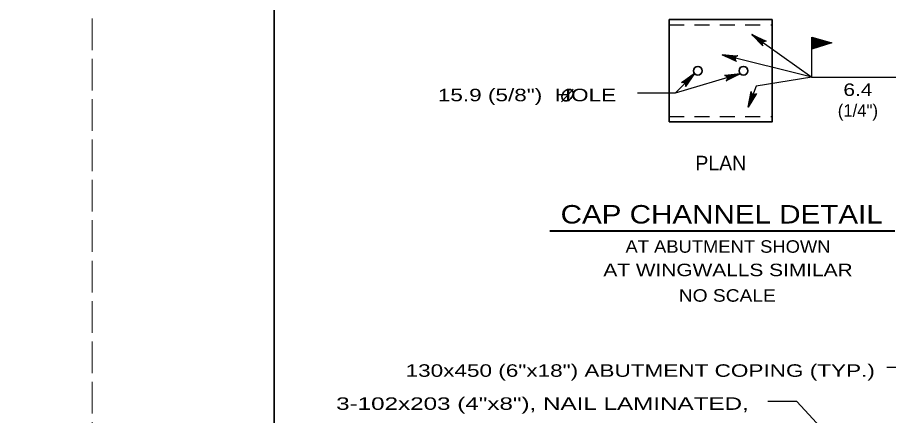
# Model space of a CAD drawing. Extents: x -6.4 to 73.1, y -66 to 0.
# Drawn here: x 33.28 to 41.66, y -58.66 to -54.84 of the extents above; entities that cross this region are included whole.
import ezdxf
from ezdxf.enums import TextEntityAlignment as Align

# ---------------------------------------------------------------- set-up
doc = ezdxf.new("R2010")
doc.units = 0
doc.header["$LTSCALE"] = 0.048
doc.linetypes.add('LONG_DASHED', pattern=[7.5, 6, -1.5])
doc.linetypes.add('MEDIUM_DASHED', pattern=[4.5, 3, -1.5])
for name, color, linetype, lineweight in [('1', 7, 'Continuous', 13), ('3', 7, 'Continuous', 35), ('4', 7, 'Continuous', 25), ('5', 7, 'Continuous', 25), ('63', 7, 'LONG_DASHED', 13)]:
    doc.layers.add(name, color=color, linetype=linetype, lineweight=lineweight)

msp = doc.modelspace()

# ---------------------------------------------------------------- linework, layer by layer
at = {"layer": '1', "lineweight": 35}
msp.add_lwpolyline([(35.75, -65.25), (67.25, -65.25), (67.25, -44.75), (35.75, -44.75)], close=True, dxfattribs=at)
at = {"layer": '3'}
for q in [(40.53625, -54.85908), (39.54658, -55.84308)]:
    msp.add_line((39.54658, -54.85908), q, dxfattribs=at)
at = {"layer": '3', "linetype": 'MEDIUM_DASHED', "lineweight": 25}
for p, q in [((39.54658, -54.91033), (40.53625, -54.91033)), ((39.54658, -55.79183), (40.53625, -55.79183))]:
    msp.add_line(p, q, dxfattribs=at)
at = {"layer": '3', "lineweight": 25}
for p, q in [((40.34167, -55.00233), (40.91958, -55.41417)), ((40.91958, -55.41417), (40.05517, -55.19875)), ((40.91958, -55.41417), (40.382, -55.50025)), ((40.91958, -55.41417), (42.10517, -55.41417)), ((40.382, -55.50025), (40.30683, -55.69967))]:
    msp.add_line(p, q, dxfattribs=at)
at = {"layer": '3'}
msp.add_lwpolyline([(39.54658, -55.84308), (40.53625, -55.84308), (40.53625, -54.85908)], dxfattribs=at)
at = {"layer": '3', "lineweight": 25}
msp.add_lwpolyline([(40.91958, -55.41417), (40.91958, -55.03017), (41.112, -55.08375), (40.91942, -55.1425), (40.92308, -55.0365), (41.09667, -55.08358), (40.92433, -55.135), (40.92433, -55.04142), (41.08617, -55.083), (40.92742, -55.13008), (40.92683, -55.047), (41.07308, -55.08358), (40.92992, -55.12508), (40.92933, -55.05383), (41.05633, -55.083), (40.94042, -55.11275), (40.933, -55.05875), (41.04525, -55.08175), (40.938, -55.11833), (40.93675, -55.06558), (41.03408, -55.08175), (40.94233, -55.11025), (40.93983, -55.07058), (41.02167, -55.08175), (40.94542, -55.1065), (40.94233, -55.073), (41.01108, -55.08175), (40.94667, -55.10283), (40.94667, -55.078), (41.00058, -55.08233), (40.94975, -55.09783), (40.94975, -55.08108), (40.98567, -55.08417), (40.95158, -55.09475), (40.95283, -55.08608), (40.97458, -55.08542), (40.95225, -55.09225), (40.95408, -55.08792), (41.10533, -55.08358), (40.9225, -55.13817), (40.92183, -55.03333)], dxfattribs=at)
at = {"layer": '3'}
for centre in [(39.82227, -55.3511), (40.26056, -55.3511)]:
    msp.add_circle(centre, 0.04217, dxfattribs=at)
at = {"layer": '4'}
for p, q in [((40.23025, -55.38042), (39.60375, -55.56533)), ((41.54783, -59.35875), (40.77258, -58.52733))]:
    msp.add_line(p, q, dxfattribs=at)
at = {"layer": '4', "lineweight": 40}
msp.add_line((38.4005, -56.88883), (41.71642, -56.88883), dxfattribs=at)
at = {"layer": '4'}
for points in [[(40.34167, -55.00233), (40.47933, -55.06617), (40.47233, -55.06608), (40.46533, -55.066), (40.46, -55.06833), (40.45467, -55.07067), (40.45108, -55.07425), (40.4475, -55.07783), (40.44533, -55.08242), (40.44308, -55.08692), (40.44258, -55.09275), (40.44208, -55.0985), (40.4445, -55.10508), (40.44683, -55.11167), (40.34167, -55.00233), (40.4445, -55.10508), (40.44208, -55.0985), (40.34167, -55.00233), (40.44258, -55.09275), (40.44308, -55.08692), (40.34167, -55.00233), (40.44533, -55.08242), (40.4475, -55.07783), (40.34167, -55.00233), (40.45108, -55.07425), (40.45467, -55.07067), (40.34167, -55.00233), (40.46, -55.06833), (40.46533, -55.066), (40.34167, -55.00233), (40.47233, -55.06608)], [(40.05517, -55.19883), (40.20667, -55.20675), (40.20017, -55.20925), (40.19367, -55.21175), (40.18958, -55.21592), (40.1855, -55.22008), (40.1835, -55.22475), (40.1815, -55.22942), (40.18117, -55.2345), (40.18083, -55.2395), (40.1825, -55.24508), (40.18425, -55.25067), (40.18883, -55.25583), (40.1935, -55.26108), (40.05517, -55.19883), (40.18883, -55.25583), (40.18425, -55.25067), (40.05517, -55.19883), (40.1825, -55.24508), (40.18083, -55.2395), (40.05517, -55.19883), (40.18117, -55.2345), (40.1815, -55.22942), (40.05517, -55.19883), (40.1835, -55.22475), (40.1855, -55.22008), (40.05517, -55.19883), (40.18958, -55.21592), (40.19367, -55.21175), (40.05517, -55.19883), (40.20017, -55.20925)], [(39.78975, -55.37792), (39.60375, -55.56533), (39.24375, -55.56533)], [(39.78975, -55.37792), (39.7045, -55.5035), (39.70575, -55.49658), (39.707, -55.48975), (39.7055, -55.48408), (39.70408, -55.4785), (39.70108, -55.47433), (39.69817, -55.47025), (39.694, -55.46733), (39.68983, -55.46442), (39.68425, -55.463), (39.67858, -55.46158), (39.67175, -55.46283), (39.66483, -55.46408), (39.78975, -55.37792), (39.67175, -55.46283), (39.67858, -55.46158), (39.78975, -55.37792), (39.68425, -55.463), (39.68983, -55.46442), (39.78975, -55.37792), (39.694, -55.46733), (39.69817, -55.47025), (39.78975, -55.37792), (39.70108, -55.47433), (39.70408, -55.4785), (39.78975, -55.37792), (39.7055, -55.48408), (39.707, -55.48975), (39.78975, -55.37792), (39.70575, -55.49658)], [(40.23025, -55.38042), (40.09508, -55.4495), (40.0995, -55.444), (40.10392, -55.43858), (40.10533, -55.43292), (40.10675, -55.42733), (40.10617, -55.42225), (40.10558, -55.41725), (40.10333, -55.41267), (40.10108, -55.40808), (40.09683, -55.40417), (40.09258, -55.40025), (40.08592, -55.398), (40.07925, -55.39583), (40.23025, -55.38042), (40.08592, -55.398), (40.09258, -55.40025), (40.23025, -55.38042), (40.09683, -55.40417), (40.10108, -55.40808), (40.23025, -55.38042), (40.10333, -55.41267), (40.10558, -55.41725), (40.23025, -55.38042), (40.10617, -55.42225), (40.10675, -55.42733), (40.23025, -55.38042), (40.10533, -55.43292), (40.10392, -55.43858), (40.23025, -55.38042), (40.0995, -55.444)], [(40.30692, -55.69967), (40.33375, -55.55033), (40.33542, -55.55717), (40.33708, -55.56392), (40.34067, -55.5685), (40.34433, -55.573), (40.34867, -55.57558), (40.35308, -55.57817), (40.35808, -55.57917), (40.363, -55.58008), (40.36875, -55.57917), (40.3745, -55.57817), (40.38025, -55.57417), (40.386, -55.57025), (40.30692, -55.69967), (40.38025, -55.57417), (40.3745, -55.57817), (40.30692, -55.69967), (40.36875, -55.57917), (40.363, -55.58008), (40.30692, -55.69967), (40.35808, -55.57917), (40.35308, -55.57817), (40.30692, -55.69967), (40.34867, -55.57558), (40.34433, -55.573), (40.30692, -55.69967), (40.34067, -55.5685), (40.33708, -55.56392), (40.30692, -55.69967), (40.33542, -55.55717)]]:
    msp.add_lwpolyline(points, dxfattribs=at)
at = {"layer": '5', "lineweight": 35}
msp.add_line((38.51208, -55.65108), (38.62408, -55.5285), dxfattribs=at)
at = {"layer": '5'}
for p, q in [((42.02283, -58.203), (41.64017, -58.203)), ((40.77258, -58.52733), (40.49508, -58.52733))]:
    msp.add_line(p, q, dxfattribs=at)
at = {"layer": '5', "lineweight": 35}
msp.add_spline([(38.61242, -55.54058), (38.60367, -55.53375), (38.59492, -55.53133), (38.58392, -55.53033), (38.57767, -55.53033), (38.56692, -55.53283), (38.55708, -55.53733), (38.55017, -55.54125), (38.53692, -55.55183), (38.52658, -55.56533), (38.52033, -55.578), (38.51667, -55.58958), (38.51558, -55.60033), (38.51667, -55.60958), (38.52117, -55.62275), (38.52592, -55.62958), (38.53558, -55.63683), (38.55008, -55.64033), (38.56658, -55.63983), (38.58742, -55.63033), (38.60267, -55.61725), (38.61417, -55.60133), (38.62167, -55.58475), (38.62417, -55.56633), (38.62092, -55.5545), (38.61292, -55.54058)], degree=3, dxfattribs=at)
at = {"layer": '63'}
for points in [[(0, -66), (34, -66), (34, -44), (0, -44)], [(34, -66), (68, -66), (68, -44), (34, -44)]]:
    msp.add_lwpolyline(points, close=True, dxfattribs=at)

# ---------------------------------------------------------------- texts
at = {"layer": '4', "width": 1.35}
msp.add_text('15.9 (5/8")  HOLE', height=0.12, dxfattribs=at).set_placement((37.32242, -55.64433))
at = {"layer": '4'}
for s, height, width, p in [('6.4', 0.12, 1.25, (41.361, -55.59325)), ('CAP CHANNEL DETAIL', 0.1772, 1.2, (40.05163, -56.81867)), ('AT ABUTMENT SHOWN', 0.12, 1.1, (40.11221, -57.09958)), ('AT WINGWALLS SIMILAR', 0.12, 1.25, (40.11221, -57.32458)), ('NO SCALE', 0.12, 1.15, (40.10567, -57.56992))]:
    msp.add_text(s, height=height, dxfattribs=dict(at, width=width)).set_placement(p, align=Align.CENTER)
for s, height, p in [('(1/4")', 0.12, (41.361, -55.79325)), ('PLAN', 0.14, (40.04296, -56.30842))]:
    msp.add_text(s, height=height, dxfattribs=at).set_placement(p, align=Align.CENTER)
at = {"layer": '5', "width": 1.35}
msp.add_text('130x450 (6"x18") ABUTMENT COPING (TYP.)', height=0.12, dxfattribs=at).set_placement((41.52408, -58.29125), align=Align.RIGHT)
at = {"layer": '5', "width": 1.45}
msp.add_text('3-102x203 (4"x8"), NAIL LAMINATED,', height=0.12, dxfattribs=at).set_placement((36.34492, -58.60875))

doc.saveas('drawing.dxf')
